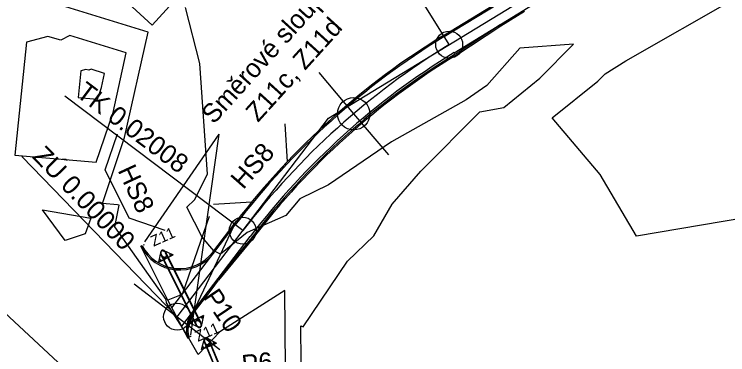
# Model space of a CAD drawing. Extents: x -549394 to -546608, y -1037055 to -1033629.
# Drawn here: x -547431.1 to -547298.7, y -1035265.1 to -1035202 of the extents above; entities that cross this region are included whole.
import ezdxf

# ---------------------------------------------------------------- set-up
doc = ezdxf.new("R2010")
doc.units = 0
for name, color, linetype in [('hlavni_vrst', 7, 'Continuous'), ('hrana_L', 7, 'Continuous'), ('norm_vrst', 7, 'Continuous'), ('POLYGONY_SITUACE_PO', 7, 'Continuous'), ('u_sirka_1_0m', 7, 'Continuous'), ('x_navrh_C14', 7, 'Continuous'), ('x_osa_C14', 7, 'Continuous'), ('x_popis_C14', 7, 'Continuous'), ('x_popis_C21', 7, 'Continuous'), ('x_popis_oblouky_C14', 7, 'Continuous'), ('x_popis_pricne_rezy_C14', 7, 'Continuous'), ('x_propustek', 7, 'Continuous'), ('x_SDZ_C141', 7, 'Continuous')]:
    doc.layers.add(name, color=color, linetype=linetype)

msp = doc.modelspace()

# ---------------------------------------------------------------- linework, layer by layer
at = {"layer": 'hlavni_vrst'}
for p, q in [((-547317.64, -1035210.67), (-547292.9, -1035196.54)), ((-547321.49, -1035213.06), (-547317.64, -1035210.67)), ((-547322.82, -1035214.4), (-547321.49, -1035213.06)), ((-547331.31, -1035221.25), (-547322.82, -1035214.4)), ((-547322.39, -1035231.75), (-547331.31, -1035221.25)), ((-547225.89, -1035228.02), (-547315.67, -1035243.17)), ((-547315.67, -1035243.17), (-547322.39, -1035231.75))]:
    msp.add_line(p, q, dxfattribs=at)
at = {"layer": 'hrana_L'}
for p, q in [((-547394.93, -1035239.52), (-547399.91, -1035253.77)), ((-547389.94, -1035240.31), (-547397.57, -1035256.44)), ((-547400.47, -1035254.17), (-547402.61, -1035255)), ((-547399.91, -1035253.77), (-547400.47, -1035254.17)), ((-547397.57, -1035256.44), (-547399.19, -1035261.16))]:
    msp.add_line(p, q, dxfattribs=at)
at = {"layer": 'norm_vrst'}
for p, q in [((-547406.29, -1035205.37), (-547424.77, -1035199.66)), ((-547396.7, -1035211.13), (-547399.36, -1035200.76)), ((-547410.63, -1035224.86), (-547406.29, -1035205.37)), ((-547424.86, -1035206.17), (-547428.84, -1035207.19)), ((-547422.5, -1035206.81), (-547424.86, -1035206.17)), ((-547420.81, -1035205.94), (-547422.5, -1035206.81)), ((-547410.33, -1035209.17), (-547420.81, -1035205.94)), ((-547428.84, -1035207.19), (-547430.99, -1035228.15)), ((-547327.34, -1035207.57), (-547337.3, -1035208.32)), ((-547333.56, -1035213.85), (-547327.34, -1035207.57)), ((-547412.79, -1035220.23), (-547410.33, -1035209.17)), ((-547337.3, -1035208.32), (-547343.44, -1035215.22)), ((-547395.23, -1035231.65), (-547396.7, -1035211.13)), ((-547418.75, -1035212.51), (-547419.26, -1035217.47)), ((-547417.81, -1035212.27), (-547418.75, -1035212.51)), ((-547417.25, -1035212.42), (-547417.81, -1035212.27)), ((-547416.85, -1035212.21), (-547417.25, -1035212.42)), ((-547414.37, -1035212.98), (-547416.85, -1035212.21)), ((-547414.95, -1035215.6), (-547414.37, -1035212.98)), ((-547340.29, -1035219.28), (-547333.56, -1035213.85)), ((-547415.69, -1035217.78), (-547414.95, -1035215.6)), ((-547343.44, -1035215.22), (-547347.28, -1035217.87)), ((-547419.26, -1035217.47), (-547415.69, -1035217.78)), ((-547347.28, -1035217.87), (-547361.11, -1035225.68)), ((-547355.64, -1035231.11), (-547344.71, -1035220.1)), ((-547344.71, -1035220.1), (-547340.29, -1035219.28)), ((-547415.9, -1035229.47), (-547412.79, -1035220.23)), ((-547414.74, -1035237.07), (-547410.63, -1035224.86)), ((-547361.11, -1035225.68), (-547372.79, -1035233.63)), ((-547430.99, -1035228.15), (-547415.9, -1035229.47)), ((-547397.67, -1035236.39), (-547395.23, -1035231.65)), ((-547361.01, -1035237.24), (-547355.64, -1035231.11)), ((-547372.79, -1035233.63), (-547378.1, -1035236.22)), ((-547411.98, -1035237.37), (-547414.74, -1035237.07)), ((-547399.08, -1035237.78), (-547397.67, -1035236.39)), ((-547378.1, -1035236.22), (-547380.73, -1035239.35)), ((-547364.39, -1035243.11), (-547361.01, -1035237.24)), ((-547421.66, -1035243.97), (-547425.85, -1035238.28)), ((-547425.85, -1035238.28), (-547416.89, -1035239.8)), ((-547412.42, -1035241.42), (-547411.63, -1035237.42)), ((-547411.63, -1035237.42), (-547411.98, -1035237.37)), ((-547396.27, -1035243.34), (-547399.08, -1035237.78)), ((-547416.89, -1035239.8), (-547417.98, -1035242.69)), ((-547380.73, -1035239.35), (-547387.91, -1035242.46)), ((-547402.94, -1035254.86), (-547412.42, -1035241.42)), ((-547387.91, -1035242.46), (-547392.85, -1035246.47)), ((-547417.98, -1035242.69), (-547421.66, -1035243.97)), ((-547394.05, -1035245.85), (-547396.27, -1035243.34)), ((-547369.28, -1035247.8), (-547364.39, -1035243.11)), ((-547392.85, -1035246.47), (-547394.05, -1035245.85)), ((-547377.5, -1035259.97), (-547369.28, -1035247.8)), ((-547380.88, -1035253.24), (-547392.94, -1035260.85)), ((-547380.81, -1035267.64), (-547380.88, -1035253.24)), ((-547402.86, -1035255.5), (-547402.94, -1035254.86)), ((-547399.19, -1035261.16), (-547402.86, -1035255.5)), ((-547421.19, -1035268.25), (-547432.95, -1035257.28)), ((-547377.89, -1035266.54), (-547377.92, -1035259.76)), ((-547377.92, -1035259.76), (-547377.5, -1035259.97)), ((-547399.19, -1035261.16), (-547399.19, -1035261.16)), ((-547399.19, -1035261.16), (-547399.19, -1035261.16)), ((-547396.98, -1035265.09), (-547399.19, -1035261.16)), ((-547399.19, -1035261.16), (-547399.19, -1035261.16)), ((-547392.94, -1035260.85), (-547396.98, -1035265.09))]:
    msp.add_line(p, q, dxfattribs=at)
at = {"layer": 'POLYGONY_SITUACE_PO'}
for centre in [(-547350.41, -1035207.65), (-547388.71, -1035242.13), (-547400.9, -1035258.08)]:
    msp.add_circle(centre, 2.5, dxfattribs=at)
at = {"layer": 'u_sirka_1_0m'}
msp.add_circle((-547368.14, -1035220.47), 3, dxfattribs=at)
at = {"layer": 'x_navrh_C14'}
for p, q in [((-547351.45, -1035205.95), (-547329.98, -1035192.84)), ((-547351.32, -1035206.16), (-547329.85, -1035193.06)), ((-547349.5, -1035209.15), (-547328.02, -1035196.04)), ((-547340.83, -1035204.15), (-547336.43, -1035201.47)), ((-547349.32, -1035209.44), (-547340.96, -1035203.94)), ((-547349.19, -1035209.65), (-547340.83, -1035204.15)), ((-547401.85, -1035256.44), (-547390.1, -1035241.07)), ((-547394.28, -1035246.13), (-547389.93, -1035240.44)), ((-547400.04, -1035259.84), (-547387.32, -1035243.19)), ((-547387.05, -1035243.4), (-547393.39, -1035251.14)), ((-547386.85, -1035243.56), (-547393.19, -1035251.29)), ((-547407.6, -1035244.99), (-547407.37, -1035244.88)), ((-547394.6, -1035253.13), (-547393.19, -1035251.29)), ((-547397.93, -1035257.49), (-547394.6, -1035253.13)), ((-547398.85, -1035262.09), (-547398.67, -1035261.86))]:
    msp.add_line(p, q, dxfattribs=at)
for points in [[(-547380.88, -1035222.31), (-547380.45, -1035229.37), (-547387.07, -1035236.86), (-547394.13, -1035237.29)], [(-547403.13, -1035242.13), (-547409.82, -1035239.84), (-547414.22, -1035230.86), (-547411.93, -1035224.17)], [(-547398.85, -1035262.09), (-547402.61, -1035255), (-547407.6, -1035244.99)]]:
    msp.add_lwpolyline(points, dxfattribs=at)
for centre, radius, start, end in [((-547277.49, -1035327.16), 141.75, 121.3907, 142.6009), ((-547277.49, -1035327.16), 142, 121.3907, 142.3575), ((-547277.49, -1035327.16), 138.25, 121.3907, 142.6009), ((-547277.49, -1035327.16), 137.91, 121.3907, 142.6009), ((-547277.49, -1035327.16), 137.66, 121.3889, 142.6027), ((-547400.44, -1035241.42), 8, 206.4879, 322.6009), ((-547400.44, -1035241.42), 7.75, 206.4879, 322.6009), ((-547394.16, -1035260.37), 5, 142.6009, 200.0463), ((-547394.16, -1035260.37), 4.75, 142.6009, 198.2348)]:
    msp.add_arc(centre, radius, start, end, dxfattribs=at)
at = {"layer": 'x_osa_C14'}
for points in [[(-547372.79, -1035221.31), (-547307.02, -1035181.18)], [(-547400.9, -1035258.08), (-547372.79, -1035221.31)]]:
    msp.add_lwpolyline(points, dxfattribs=at)
msp.add_arc((-547277.49, -1035327.16), 140, 121.3907, 142.6009, dxfattribs=at)
at = {"layer": 'x_popis_oblouky_C14'}
for points in [[(-547350.41, -1035207.65), (-547372.32, -1035172.56)], [(-547388.71, -1035242.13), (-547421.72, -1035217.2)], [(-547400.9, -1035258.08), (-547429.73, -1035228.4)]]:
    msp.add_lwpolyline(points, dxfattribs=at)
msp.add_lwpolyline([(-547409.95, -1035200), (-547389.74, -1035177.83), (-547385.31, -1035181.87), (-547405.51, -1035204.05)], close=True, dxfattribs=at)
at = {"layer": 'x_popis_pricne_rezy_C14'}
for points in [[(-547374.61, -1035212.85), (-547368.14, -1035220.47), (-547361.66, -1035228.1)], [(-547408.84, -1035252.01), (-547400.9, -1035258.08), (-547392.96, -1035264.15)]]:
    msp.add_lwpolyline(points, dxfattribs=at)
at = {"layer": 'x_propustek'}
for p, q in [((-547404.31, -1035247.98), (-547403.88, -1035245.95)), ((-547403.5, -1035245.76), (-547403.88, -1035245.95)), ((-547403.5, -1035245.76), (-547401.62, -1035246.64)), ((-547396.57, -1035259.21), (-547403.02, -1035246.28)), ((-547396.5, -1035259.17), (-547402.95, -1035246.25)), ((-547402.05, -1035246.85), (-547402.22, -1035246.49)), ((-547404.31, -1035247.98), (-547401.62, -1035246.64)), ((-547403.88, -1035247.77), (-547404.06, -1035247.41)), ((-547403.97, -1035247.82), (-547404.06, -1035247.64)), ((-547403.79, -1035247.73), (-547403.88, -1035247.55)), ((-547397.37, -1035259.61), (-547403.83, -1035246.68)), ((-547397.31, -1035259.58), (-547403.76, -1035246.65)), ((-547402.13, -1035246.9), (-547402.22, -1035246.72)), ((-547401.96, -1035246.81), (-547402.04, -1035246.63)), ((-547396.02, -1035257.87), (-547398.7, -1035259.21)), ((-547396.53, -1035258.13), (-547396.44, -1035258.31)), ((-547396.02, -1035257.87), (-547396.44, -1035259.9)), ((-547396.44, -1035258.08), (-547396.26, -1035258.44)), ((-547396.35, -1035258.04), (-547396.26, -1035258.22)), ((-547396.82, -1035260.09), (-547398.7, -1035259.21)), ((-547398.37, -1035259.05), (-547398.28, -1035259.23)), ((-547398.28, -1035259), (-547398.1, -1035259.36)), ((-547398.19, -1035258.96), (-547398.1, -1035259.14)), ((-547396.82, -1035260.09), (-547396.44, -1035259.9)), ((-547396.35, -1035264.17), (-547395.79, -1035262.17)), ((-547395.39, -1035262.01), (-547395.79, -1035262.17)), ((-547395.39, -1035262.01), (-547393.58, -1035263.01)), ((-547396.35, -1035264.17), (-547393.58, -1035263.01)), ((-547395.91, -1035263.98), (-547396.07, -1035263.61)), ((-547395.82, -1035263.94), (-547395.9, -1035263.76)), ((-547390.99, -1035274.38), (-547395.78, -1035262.9)), ((-547390.92, -1035274.35), (-547395.71, -1035262.87)), ((-547390.16, -1035274.03), (-547394.95, -1035262.55)), ((-547390.09, -1035274), (-547394.88, -1035262.52)), ((-547394.11, -1035263.23), (-547394.18, -1035263.04)), ((-547394.02, -1035263.19), (-547394.17, -1035262.82)), ((-547393.92, -1035263.15), (-547394, -1035262.97)), ((-547396, -1035264.02), (-547396.08, -1035263.84))]:
    msp.add_line(p, q, dxfattribs=at)
for points in [[(-547403.72, -1035245.79), (-547403.74, -1035245.8), (-547403.75, -1035245.81), (-547403.78, -1035245.82), (-547403.79, -1035245.83), (-547403.83, -1035245.87), (-547403.85, -1035245.89), (-547403.9, -1035245.98), (-547403.92, -1035246.05), (-547403.94, -1035246.22), (-547403.94, -1035246.31), (-547403.9, -1035246.5), (-547403.87, -1035246.59), (-547403.78, -1035246.77), (-547403.72, -1035246.85), (-547403.6, -1035247), (-547403.53, -1035247.05), (-547403.38, -1035247.14), (-547403.31, -1035247.16), (-547403.22, -1035247.17), (-547403.21, -1035247.17), (-547403.17, -1035247.17), (-547403.16, -1035247.17), (-547403.11, -1035247.16), (-547403.08, -1035247.15), (-547403.05, -1035247.14)], [(-547403.69, -1035245.86), (-547403.71, -1035245.87), (-547403.73, -1035245.88), (-547403.77, -1035245.92), (-547403.79, -1035245.94), (-547403.81, -1035245.99), (-547403.83, -1035246.01), (-547403.85, -1035246.07), (-547403.86, -1035246.11), (-547403.86, -1035246.18), (-547403.87, -1035246.22), (-547403.86, -1035246.31), (-547403.86, -1035246.35), (-547403.83, -1035246.48), (-547403.8, -1035246.56), (-547403.72, -1035246.73), (-547403.66, -1035246.81), (-547403.58, -1035246.91), (-547403.55, -1035246.94), (-547403.48, -1035246.99), (-547403.45, -1035247.01), (-547403.39, -1035247.05), (-547403.35, -1035247.06), (-547403.29, -1035247.09), (-547403.26, -1035247.09), (-547403.21, -1035247.1), (-547403.18, -1035247.1), (-547403.13, -1035247.09), (-547403.11, -1035247.08), (-547403.06, -1035247.06), (-547403.04, -1035247.04), (-547403.01, -1035247.01), (-547402.99, -1035246.99), (-547402.96, -1035246.94), (-547402.95, -1035246.91), (-547402.93, -1035246.85), (-547402.92, -1035246.82), (-547402.91, -1035246.74), (-547402.91, -1035246.7), (-547402.92, -1035246.62), (-547402.92, -1035246.58), (-547402.95, -1035246.45), (-547402.98, -1035246.36), (-547403.06, -1035246.19), (-547403.11, -1035246.12), (-547403.2, -1035246.02), (-547403.23, -1035245.99), (-547403.29, -1035245.94), (-547403.33, -1035245.92), (-547403.39, -1035245.88), (-547403.42, -1035245.86), (-547403.49, -1035245.84), (-547403.52, -1035245.84), (-547403.57, -1035245.83), (-547403.6, -1035245.83), (-547403.65, -1035245.84), (-547403.67, -1035245.85), (-547403.69, -1035245.86)], [(-547403.05, -1035247.14), (-547403.04, -1035247.13), (-547403.02, -1035247.12), (-547403, -1035247.1), (-547402.99, -1035247.09), (-547402.95, -1035247.06), (-547402.93, -1035247.03), (-547402.88, -1035246.95), (-547402.85, -1035246.87), (-547402.83, -1035246.71), (-547402.84, -1035246.62), (-547402.87, -1035246.43), (-547402.91, -1035246.34), (-547403, -1035246.16), (-547403.05, -1035246.07), (-547403.18, -1035245.93), (-547403.25, -1035245.87), (-547403.39, -1035245.79), (-547403.47, -1035245.77), (-547403.55, -1035245.76), (-547403.57, -1035245.76), (-547403.6, -1035245.76), (-547403.62, -1035245.76), (-547403.67, -1035245.77), (-547403.7, -1035245.78), (-547403.72, -1035245.79)], [(-547397.27, -1035258.72), (-547397.29, -1035258.73), (-547397.3, -1035258.73), (-547397.33, -1035258.75), (-547397.34, -1035258.76), (-547397.37, -1035258.8), (-547397.39, -1035258.82), (-547397.45, -1035258.91), (-547397.47, -1035258.98), (-547397.49, -1035259.15), (-547397.49, -1035259.24), (-547397.45, -1035259.43), (-547397.42, -1035259.52), (-547397.33, -1035259.7), (-547397.27, -1035259.78), (-547397.15, -1035259.92), (-547397.08, -1035259.98), (-547396.93, -1035260.07), (-547396.86, -1035260.09), (-547396.77, -1035260.1), (-547396.76, -1035260.1), (-547396.72, -1035260.1), (-547396.71, -1035260.1), (-547396.66, -1035260.09), (-547396.63, -1035260.08), (-547396.6, -1035260.06)], [(-547396.63, -1035260), (-547396.61, -1035259.99), (-547396.59, -1035259.97), (-547396.56, -1035259.94), (-547396.54, -1035259.92), (-547396.51, -1035259.87), (-547396.5, -1035259.84), (-547396.48, -1035259.78), (-547396.47, -1035259.75), (-547396.46, -1035259.67), (-547396.46, -1035259.63), (-547396.46, -1035259.55), (-547396.47, -1035259.51), (-547396.49, -1035259.38), (-547396.52, -1035259.29), (-547396.61, -1035259.12), (-547396.66, -1035259.05), (-547396.75, -1035258.95), (-547396.78, -1035258.92), (-547396.84, -1035258.87), (-547396.87, -1035258.84), (-547396.94, -1035258.81), (-547396.97, -1035258.79), (-547397.03, -1035258.77), (-547397.06, -1035258.76), (-547397.12, -1035258.76), (-547397.15, -1035258.76), (-547397.19, -1035258.77), (-547397.22, -1035258.78), (-547397.26, -1035258.8), (-547397.28, -1035258.81), (-547397.32, -1035258.84), (-547397.33, -1035258.87), (-547397.36, -1035258.91), (-547397.37, -1035258.94), (-547397.4, -1035259), (-547397.4, -1035259.04), (-547397.41, -1035259.11), (-547397.41, -1035259.15), (-547397.41, -1035259.23), (-547397.4, -1035259.28), (-547397.38, -1035259.4), (-547397.35, -1035259.49), (-547397.26, -1035259.66), (-547397.21, -1035259.74), (-547397.12, -1035259.84), (-547397.09, -1035259.87), (-547397.03, -1035259.92), (-547397, -1035259.94), (-547396.93, -1035259.98), (-547396.9, -1035259.99), (-547396.84, -1035260.01), (-547396.81, -1035260.02), (-547396.75, -1035260.02), (-547396.73, -1035260.02), (-547396.68, -1035260.02), (-547396.66, -1035260.01), (-547396.63, -1035260)], [(-547396.6, -1035260.06), (-547396.59, -1035260.06), (-547396.57, -1035260.05), (-547396.55, -1035260.03), (-547396.53, -1035260.02), (-547396.5, -1035259.99), (-547396.48, -1035259.96), (-547396.43, -1035259.87), (-547396.4, -1035259.8), (-547396.38, -1035259.63), (-547396.39, -1035259.54), (-547396.42, -1035259.36), (-547396.45, -1035259.26), (-547396.54, -1035259.08), (-547396.6, -1035259), (-547396.73, -1035258.86), (-547396.8, -1035258.8), (-547396.94, -1035258.72), (-547397.02, -1035258.69), (-547397.1, -1035258.68), (-547397.12, -1035258.68), (-547397.15, -1035258.69), (-547397.17, -1035258.69), (-547397.21, -1035258.7), (-547397.24, -1035258.7), (-547397.27, -1035258.72)], [(-547395.62, -1035262.02), (-547395.63, -1035262.02), (-547395.65, -1035262.03), (-547395.67, -1035262.05), (-547395.69, -1035262.06), (-547395.72, -1035262.09), (-547395.75, -1035262.11), (-547395.81, -1035262.2), (-547395.84, -1035262.27), (-547395.87, -1035262.43), (-547395.87, -1035262.52), (-547395.84, -1035262.71), (-547395.82, -1035262.81), (-547395.74, -1035262.99), (-547395.69, -1035263.08), (-547395.57, -1035263.23), (-547395.51, -1035263.29), (-547395.37, -1035263.39), (-547395.3, -1035263.41), (-547395.21, -1035263.43), (-547395.2, -1035263.43), (-547395.16, -1035263.43), (-547395.15, -1035263.43), (-547395.1, -1035263.43), (-547395.07, -1035263.42), (-547395.04, -1035263.41)], [(-547395.59, -1035262.09), (-547395.61, -1035262.1), (-547395.63, -1035262.11), (-547395.67, -1035262.14), (-547395.69, -1035262.16), (-547395.72, -1035262.21), (-547395.74, -1035262.23), (-547395.76, -1035262.29), (-547395.77, -1035262.33), (-547395.78, -1035262.4), (-547395.79, -1035262.44), (-547395.79, -1035262.52), (-547395.79, -1035262.56), (-547395.77, -1035262.69), (-547395.75, -1035262.78), (-547395.67, -1035262.96), (-547395.63, -1035263.04), (-547395.55, -1035263.14), (-547395.52, -1035263.17), (-547395.46, -1035263.23), (-547395.43, -1035263.26), (-547395.37, -1035263.3), (-547395.33, -1035263.31), (-547395.27, -1035263.34), (-547395.25, -1035263.35), (-547395.19, -1035263.36), (-547395.16, -1035263.36), (-547395.11, -1035263.35), (-547395.09, -1035263.35), (-547395.05, -1035263.33), (-547395.03, -1035263.32), (-547394.99, -1035263.28), (-547394.97, -1035263.26), (-547394.94, -1035263.22), (-547394.92, -1035263.19), (-547394.9, -1035263.13), (-547394.89, -1035263.1), (-547394.87, -1035263.02), (-547394.87, -1035262.98), (-547394.87, -1035262.9), (-547394.87, -1035262.86), (-547394.89, -1035262.73), (-547394.91, -1035262.64), (-547394.98, -1035262.47), (-547395.03, -1035262.39), (-547395.11, -1035262.28), (-547395.14, -1035262.25), (-547395.2, -1035262.19), (-547395.23, -1035262.17), (-547395.29, -1035262.13), (-547395.32, -1035262.11), (-547395.38, -1035262.09), (-547395.41, -1035262.08), (-547395.47, -1035262.07), (-547395.5, -1035262.07), (-547395.54, -1035262.07), (-547395.57, -1035262.08), (-547395.59, -1035262.09)], [(-547395.04, -1035263.41), (-547395.02, -1035263.4), (-547395.01, -1035263.39), (-547394.98, -1035263.38), (-547394.97, -1035263.37), (-547394.93, -1035263.34), (-547394.91, -1035263.31), (-547394.85, -1035263.23), (-547394.82, -1035263.16), (-547394.79, -1035262.99), (-547394.79, -1035262.9), (-547394.81, -1035262.71), (-547394.84, -1035262.62), (-547394.92, -1035262.43), (-547394.97, -1035262.34), (-547395.08, -1035262.2), (-547395.15, -1035262.13), (-547395.29, -1035262.04), (-547395.36, -1035262.01), (-547395.45, -1035262), (-547395.46, -1035261.99), (-547395.5, -1035261.99), (-547395.51, -1035261.99), (-547395.56, -1035262), (-547395.59, -1035262.01), (-547395.62, -1035262.02)]]:
    msp.add_open_spline(points, degree=3, dxfattribs=at)
at = {"layer": 'x_SDZ_C141'}
for p, q in [((-547407.14, -1035244.78), (-547406.92, -1035244.67)), ((-547398.49, -1035261.74), (-547398.27, -1035261.63))]:
    msp.add_line(p, q, dxfattribs=at)
for points in [[(-547406.87, -1035244.23), (-547393.08, -1035224.25)], [(-547398.35, -1035261.46), (-547393.08, -1035224.25)]]:
    msp.add_lwpolyline(points, dxfattribs=at)

# ---------------------------------------------------------------- texts
at = {"layer": 'x_popis_C14'}
for s, rotation, p in [('HS8', 48.5917, (-547388.63, -1035234.65)), ('HS8', 294.8114, (-547411.98, -1035230.94)), ('P6', 6.4523, (-547388.69, -1035268.7))]:
    msp.add_text(s, height=3.5, rotation=rotation, dxfattribs=at).set_placement(p)
at = {"layer": 'x_popis_C21'}
msp.add_text('P10', height=3.5, rotation=304.13, dxfattribs=at).set_placement((-547396.18, -1035254.44))
at = {"layer": 'x_popis_oblouky_C14'}
for s, rotation, p in [('TK 0.02008', 322.9384, (-547419.83, -1035217.11)), ('ZÚ 0.00000', 314.1648, (-547427.92, -1035228.52))]:
    msp.add_text(s, height=3.5, rotation=rotation, dxfattribs=at).set_placement(p)
at = {"layer": 'x_SDZ_C141'}
for s, height, rotation, p in [('Směrové sloupky', 3.5, 47.8559, (-547394.1, -1035222.55)), ('Z11c, Z11d', 3.5, 47.8559, (-547385.89, -1035222.18)), ('Z11', 2, 23.9554, (-547405.27, -1035245.12)), ('Z11', 2, 23.9554, (-547397.04, -1035262.76))]:
    msp.add_text(s, height=height, rotation=rotation, dxfattribs=at).set_placement(p)

doc.saveas('drawing.dxf')
